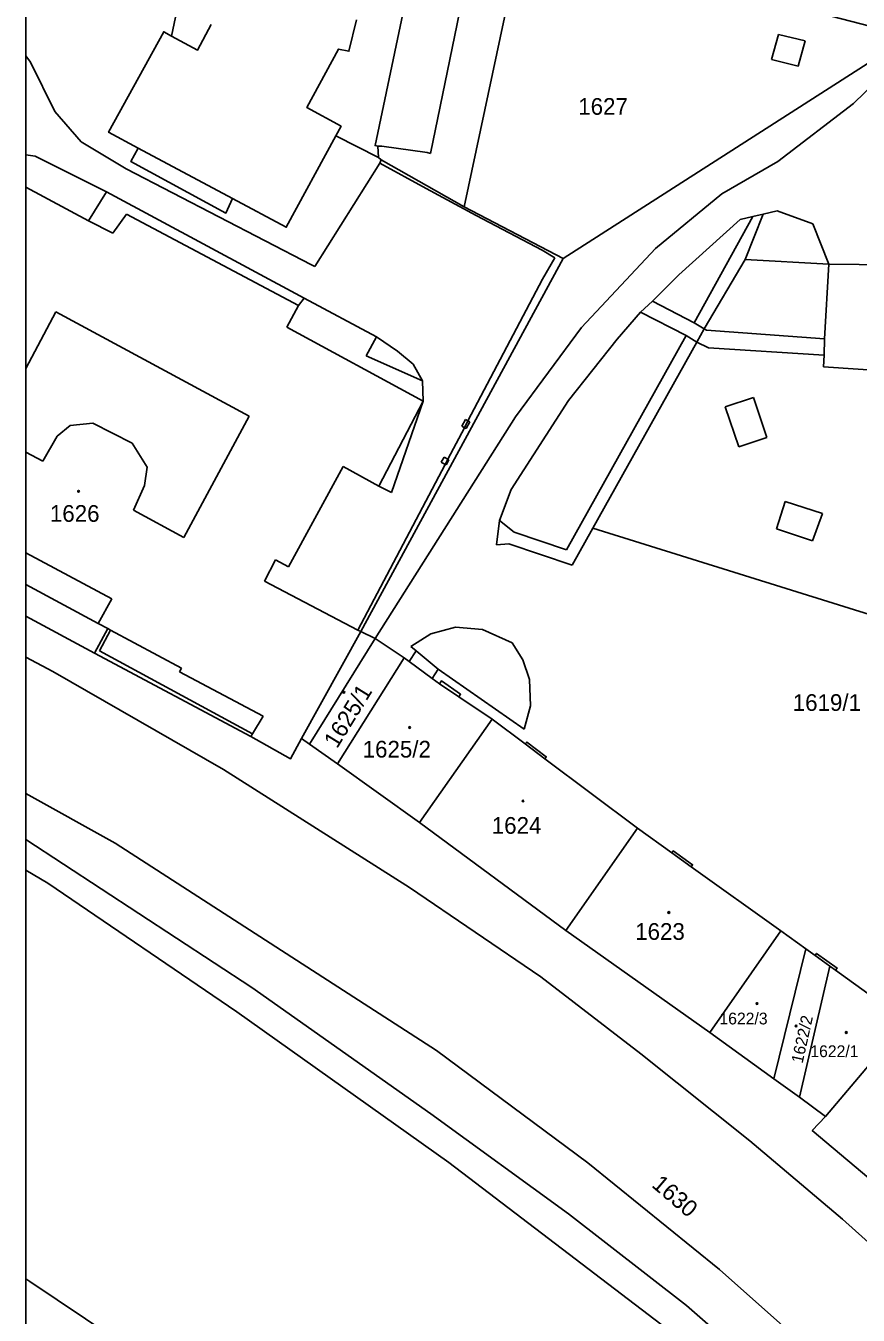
# Model space of a CAD drawing. Extents: x -598934 to -598196, y -1162208 to -1161502.
# Drawn here: x -598932 to -598847.2, y -1161742.9 to -1161611.7 of the extents above; entities that cross this region are included whole.
import ezdxf

# ---------------------------------------------------------------- set-up
doc = ezdxf.new("R2010")
doc.units = 0
for name, color, linetype in [('KN_CAR_KR', 7, 'Continuous'), ('KN_KULTURY', 7, 'Continuous'), ('KN_PARC_CIS_POZ', 7, 'Continuous'), ('KN_PARC_CIS_STAV', 7, 'Continuous'), ('KN_PARC_PLOCHA', 7, 'Continuous'), ('parcely_l', 7, 'Continuous')]:
    doc.layers.add(name, color=color, linetype=linetype)

msp = doc.modelspace()

# ---------------------------------------------------------------- linework, layer by layer
at = {"layer": 'KN_CAR_KR'}
for points in [[(-598886.11, -1161601.84), (-598890.79, -1161624.66)], [(-598856.06, -1161615.09), (-598855.34, -1161612.52)], [(-598855.34, -1161612.52), (-598852.61, -1161613.18)], [(-598852.61, -1161613.18), (-598853.33, -1161615.77)], [(-598847.69, -1161619.55), (-598841.83, -1161613.85)], [(-598931.53, -1161615.36), (-598932.02, -1161614.7)], [(-598929.05, -1161620.37), (-598931.53, -1161615.36)], [(-598853.33, -1161615.77), (-598856.06, -1161615.09)], [(-598855.42, -1161625.45), (-598847.69, -1161619.55)], [(-598929.05, -1161620.37), (-598926.37, -1161623.46)], [(-598926.37, -1161623.46), (-598921.78, -1161626.22)], [(-598932.02, -1161624.79), (-598931.06, -1161624.91)], [(-598920.57, -1161624.1), (-598910.96, -1161629.23)], [(-598895.75, -1161623.9), (-598896.15, -1161623.89)], [(-598895.75, -1161623.9), (-598891.14, -1161624.54)], [(-598891.14, -1161624.54), (-598890.79, -1161624.66)], [(-598931.06, -1161624.91), (-598923.81, -1161628.54)], [(-598895.95, -1161625.63), (-598902.56, -1161636.15)], [(-598895.95, -1161625.63), (-598895.81, -1161625.3)], [(-598891.23, -1161628.22), (-598895.95, -1161625.63)], [(-598861.13, -1161628.76), (-598855.42, -1161625.45)], [(-598902.9, -1161636), (-598921.78, -1161626.22)], [(-598932.02, -1161628.07), (-598925.62, -1161631.51)], [(-598925.62, -1161631.51), (-598923.81, -1161628.54)], [(-598923.81, -1161628.54), (-598903.67, -1161639.39)], [(-598886.15, -1161630.97), (-598891.23, -1161628.22)], [(-598867.86, -1161634.33), (-598861.13, -1161628.76)], [(-598923.14, -1161632.76), (-598921.75, -1161630.82)], [(-598921.75, -1161630.82), (-598904.23, -1161640.13)], [(-598879.42, -1161634.48), (-598886.15, -1161630.97)], [(-598859.26, -1161631.38), (-598865.48, -1161636.99)], [(-598857.96, -1161631.07), (-598863.92, -1161641.9)], [(-598859.26, -1161631.38), (-598857.96, -1161631.07)], [(-598856.92, -1161630.83), (-598858.75, -1161635.43)], [(-598857.96, -1161631.07), (-598856.92, -1161630.83)], [(-598856.92, -1161630.83), (-598855.48, -1161630.49)], [(-598851.83, -1161631.82), (-598855.48, -1161630.49)], [(-598925.62, -1161631.51), (-598923.14, -1161632.76)], [(-598851.83, -1161631.82), (-598850.21, -1161635.93)], [(-598878.13, -1161635.28), (-598879.42, -1161634.48)], [(-598879.37, -1161637.43), (-598878.13, -1161635.28)], [(-598875.42, -1161642.37), (-598867.86, -1161634.33)], [(-598902.56, -1161636.15), (-598902.9, -1161636)], [(-598850.21, -1161635.93), (-598850.65, -1161643.52)], [(-598886.97, -1161651.88), (-598879.37, -1161637.43)], [(-598865.48, -1161636.99), (-598868.19, -1161639.67)], [(-598904.23, -1161640.13), (-598905.44, -1161642.33)], [(-598903.67, -1161639.39), (-598904.23, -1161640.13)], [(-598903.67, -1161639.39), (-598896.29, -1161643.33)], [(-598868.19, -1161639.67), (-598869.39, -1161640.79)], [(-598868.19, -1161639.67), (-598863.92, -1161641.9)], [(-598932.02, -1161646.53), (-598928.94, -1161640.76)], [(-598928.94, -1161640.76), (-598909.26, -1161651.41)], [(-598869.39, -1161640.79), (-598871.76, -1161643.56)], [(-598864.74, -1161643.18), (-598869.39, -1161640.79)], [(-598863.92, -1161641.9), (-598862.92, -1161642.5)], [(-598905.44, -1161642.33), (-598891.52, -1161649.85)], [(-598882.13, -1161651.46), (-598875.42, -1161642.37)], [(-598864.74, -1161643.18), (-598876.93, -1161664.99)], [(-598863.67, -1161643.85), (-598864.74, -1161643.18)], [(-598862.92, -1161642.5), (-598862.67, -1161642.64)], [(-598862.67, -1161642.64), (-598850.65, -1161643.52)], [(-598897.34, -1161645.25), (-598896.29, -1161643.33)], [(-598896.29, -1161643.33), (-598894.14, -1161644.76)], [(-598876.73, -1161649.79), (-598871.76, -1161643.56)], [(-598863.67, -1161643.85), (-598862.47, -1161644.44)], [(-598850.68, -1161645.2), (-598862.47, -1161644.44)], [(-598850.65, -1161643.52), (-598850.68, -1161645.2)], [(-598891.6, -1161647.81), (-598897.34, -1161645.25)], [(-598894.14, -1161644.76), (-598892.56, -1161646.1)], [(-598850.68, -1161645.2), (-598850.77, -1161646.37)], [(-598892.56, -1161646.1), (-598891.6, -1161647.81)], [(-598850.77, -1161646.37), (-598823.48, -1161648.19)], [(-598891.6, -1161647.81), (-598891.52, -1161649.85)], [(-598876.73, -1161649.79), (-598882.56, -1161658.86)], [(-598860.79, -1161650.43), (-598857.88, -1161649.5)], [(-598857.88, -1161649.5), (-598856.52, -1161653.56)], [(-598891.52, -1161649.85), (-598896.06, -1161658.53)], [(-598891.52, -1161649.85), (-598894.77, -1161659.17)], [(-598859.38, -1161654.5), (-598860.79, -1161650.43)], [(-598928.81, -1161653.42), (-598927.48, -1161652.33)], [(-598925.19, -1161652.11), (-598927.48, -1161652.33)], [(-598921.17, -1161654.13), (-598925.19, -1161652.11)], [(-598909.26, -1161651.41), (-598915.91, -1161663.73)], [(-598882.13, -1161651.46), (-598896.44, -1161674.02)], [(-598887.6, -1161652.42), (-598887.24, -1161651.74)], [(-598887.33, -1161652.57), (-598887.6, -1161652.42)], [(-598887.33, -1161652.57), (-598886.97, -1161651.88)], [(-598887.24, -1161651.74), (-598886.97, -1161651.88)], [(-598886.79, -1161651.98), (-598887.16, -1161652.66)], [(-598886.97, -1161651.88), (-598886.79, -1161651.98)], [(-598928.81, -1161653.42), (-598930.28, -1161655.99)], [(-598889.02, -1161655.77), (-598887.33, -1161652.57)], [(-598887.16, -1161652.66), (-598887.33, -1161652.57)], [(-598856.52, -1161653.56), (-598859.38, -1161654.5)], [(-598930.28, -1161655.99), (-598932.02, -1161655.06)], [(-598921.17, -1161654.13), (-598919.64, -1161656.57)], [(-598898.18, -1161673.18), (-598889.3, -1161656.3)], [(-598889.72, -1161656.09), (-598889.39, -1161655.58)], [(-598889.3, -1161656.3), (-598889.72, -1161656.09)], [(-598889.39, -1161655.58), (-598889.02, -1161655.77)], [(-598889.3, -1161656.3), (-598889.02, -1161655.77)], [(-598889.2, -1161656.35), (-598889.3, -1161656.3)], [(-598888.91, -1161655.83), (-598889.2, -1161656.35)], [(-598889.02, -1161655.77), (-598888.91, -1161655.83)], [(-598919.93, -1161658.45), (-598919.64, -1161656.57)], [(-598899.68, -1161656.53), (-598905.24, -1161666.72)], [(-598896.06, -1161658.53), (-598899.68, -1161656.53)], [(-598921.05, -1161660.97), (-598919.93, -1161658.45)], [(-598894.77, -1161659.17), (-598896.06, -1161658.53)], [(-598883.77, -1161662), (-598882.56, -1161658.86)], [(-598855.55, -1161662.85), (-598854.65, -1161660.09)], [(-598854.65, -1161660.09), (-598850.85, -1161661.29)], [(-598915.91, -1161663.73), (-598921.05, -1161660.97)], [(-598850.85, -1161661.29), (-598851.89, -1161664.07)], [(-598883.77, -1161662), (-598884.08, -1161664.51)], [(-598882.28, -1161663.21), (-598883.77, -1161662)], [(-598876.36, -1161666.56), (-598874.24, -1161662.79)], [(-598851.89, -1161664.07), (-598855.55, -1161662.85)], [(-598876.93, -1161664.99), (-598882.28, -1161663.21)], [(-598932.02, -1161665.3), (-598923.24, -1161669.98)], [(-598884.08, -1161664.51), (-598882.81, -1161664.38)], [(-598882.81, -1161664.38), (-598876.36, -1161666.56)], [(-598906.57, -1161666.02), (-598907.71, -1161668.2)], [(-598905.24, -1161666.72), (-598906.57, -1161666.02)], [(-598907.71, -1161668.2), (-598898.18, -1161673.18)], [(-598932.02, -1161668.53), (-598924.63, -1161672.49)], [(-598923.24, -1161669.98), (-598924.63, -1161672.49)], [(-598925.01, -1161675.53), (-598923.66, -1161673.02)], [(-598923.66, -1161673.02), (-598924.63, -1161672.49)], [(-598924.52, -1161675.27), (-598923.37, -1161673.19)], [(-598923.37, -1161673.19), (-598923.66, -1161673.02)], [(-598916.14, -1161677.06), (-598923.37, -1161673.19)], [(-598898.18, -1161673.18), (-598897.88, -1161673.33)], [(-598888.23, -1161672.88), (-598890.75, -1161673.55)], [(-598888.23, -1161672.88), (-598885.49, -1161673.13)], [(-598882.47, -1161674.47), (-598885.49, -1161673.13)], [(-598903.12, -1161684.79), (-598896.44, -1161674.02)], [(-598892.78, -1161674.83), (-598890.75, -1161673.55)], [(-598882.47, -1161674.47), (-598881.37, -1161676.21)], [(-598932.02, -1161675.92), (-598929.26, -1161677.4)], [(-598908.92, -1161683.75), (-598924.52, -1161675.27)], [(-598892.97, -1161676.37), (-598892.24, -1161675.28)], [(-598892.24, -1161675.28), (-598892.78, -1161674.83)], [(-598892.24, -1161675.28), (-598890.01, -1161677.14)], [(-598929.26, -1161677.4), (-598911.88, -1161687.37)], [(-598916.35, -1161677.43), (-598916.14, -1161677.06)], [(-598890.01, -1161677.14), (-598890.63, -1161678.11)], [(-598881.25, -1161683.27), (-598890.01, -1161677.14)], [(-598880.71, -1161678.19), (-598881.37, -1161676.21)], [(-598907.85, -1161681.92), (-598916.35, -1161677.43)], [(-598887.9, -1161679.96), (-598889.87, -1161678.63)], [(-598880.71, -1161678.19), (-598880.61, -1161680.89)], [(-598881.25, -1161683.27), (-598880.61, -1161680.89)], [(-598908.92, -1161683.75), (-598907.85, -1161681.92)], [(-598909.09, -1161684.01), (-598908.92, -1161683.75)], [(-598879.15, -1161686.27), (-598881.14, -1161684.77)], [(-598911.88, -1161687.37), (-598892.94, -1161699.39)], [(-598932.02, -1161689.81), (-598922.91, -1161694.88)], [(-598908.99, -1161709.55), (-598932.02, -1161694.49)], [(-598890.19, -1161715.97), (-598922.91, -1161694.88)], [(-598864.23, -1161697.26), (-598866.21, -1161695.85)], [(-598892.94, -1161699.39), (-598879.55, -1161708.46)], [(-598849.53, -1161707.8), (-598850.1, -1161707.39)], [(-598869.36, -1161716.33), (-598879.55, -1161708.46)], [(-598908.99, -1161709.55), (-598890.77, -1161722.43)], [(-598890.19, -1161715.97), (-598874.78, -1161727.42)], [(-598869.36, -1161716.33), (-598858.27, -1161725.17)], [(-598876.72, -1161732.62), (-598890.77, -1161722.43)], [(-598858.27, -1161725.17), (-598848.83, -1161733.15)], [(-598861.34, -1161738.27), (-598874.78, -1161727.42)], [(-598876.72, -1161732.62), (-598864.7, -1161741.93)], [(-598834.64, -1161745.86), (-598848.83, -1161733.15)], [(-598861.34, -1161738.27), (-598850.63, -1161747.82)], [(-598864.7, -1161741.93), (-598839.67, -1161763.81)]]:
    msp.add_lwpolyline(points, dxfattribs=at)
at = {"layer": 'KN_KULTURY'}
for centre, radius in [((-598926.64, -1161659.05), 0.09), ((-598926.64, -1161659.05), 0.0398), ((-598899.62, -1161679.5), 0.09), ((-598899.62, -1161679.5), 0.0398), ((-598892.91, -1161683.09), 0.09), ((-598892.91, -1161683.09), 0.0398), ((-598881.37, -1161690.57), 0.09), ((-598881.37, -1161690.57), 0.0398), ((-598866.51, -1161701.93), 0.09), ((-598866.51, -1161701.93), 0.0398), ((-598857.53, -1161711.2), 0.09), ((-598857.53, -1161711.2), 0.0398), ((-598853.55, -1161713.48), 0.09), ((-598853.55, -1161713.48), 0.0398), ((-598848.44, -1161714.14), 0.09), ((-598848.44, -1161714.14), 0.0398)]:
    msp.add_circle(centre, radius, dxfattribs=at)
at = {"layer": 'KN_PARC_PLOCHA'}
for points in [[(-598907.97, -1161569.08), (-598917.18, -1161612.69), (-598917.96, -1161612.26), (-598923.58, -1161622.49), (-598920.57, -1161624.1), (-598921.32, -1161625.46), (-598911.63, -1161630.71), (-598910.96, -1161629.23), (-598905.49, -1161632.16), (-598900.43, -1161622.86), (-598896.1, -1161625.05), (-598895.81, -1161625.3), (-598887.35, -1161630.07), (-598877.29, -1161635.33), (-598897.88, -1161673.33), (-598903.94, -1161684.22), (-598905.05, -1161686.28), (-598909.09, -1161684.01), (-598925.01, -1161675.53), (-598932.02, -1161671.76), (-598932.02, -1161526.32)], [(-598913.14, -1161611.53), (-598914.54, -1161614.14), (-598917.18, -1161612.69), (-598907.97, -1161569.08)], [(-598891.02, -1161598.13), (-598896.44, -1161623.85), (-598896.15, -1161623.89), (-598896.1, -1161625.05), (-598900.43, -1161622.86), (-598899.89, -1161621.87), (-598903.38, -1161619.97), (-598900.15, -1161614.03), (-598899.1, -1161614.24), (-598898.32, -1161611.04)], [(-598881.6, -1161602.96), (-598887.35, -1161630.07), (-598895.81, -1161625.3), (-598896.1, -1161625.05), (-598896.15, -1161623.89), (-598896.44, -1161623.85), (-598891.02, -1161598.13)], [(-598898.32, -1161611.04), (-598899.1, -1161614.24), (-598900.15, -1161614.03), (-598903.38, -1161619.97), (-598899.89, -1161621.87), (-598900.43, -1161622.86), (-598905.49, -1161632.16), (-598910.96, -1161629.23), (-598911.63, -1161630.71), (-598921.32, -1161625.46), (-598920.57, -1161624.1), (-598923.58, -1161622.49), (-598917.96, -1161612.26), (-598917.18, -1161612.69), (-598914.54, -1161614.14), (-598913.14, -1161611.53)], [(-598842.34, -1161713), (-598849.53, -1161707.8), (-598849.38, -1161707.59), (-598851.47, -1161706.09), (-598851.62, -1161706.29), (-598852.55, -1161705.62), (-598855.09, -1161703.78), (-598864.23, -1161697.26), (-598864.09, -1161697.06), (-598866.06, -1161695.65), (-598866.21, -1161695.85), (-598869.71, -1161693.35), (-598879.15, -1161686.27), (-598879, -1161686.07), (-598880.99, -1161684.57), (-598881.14, -1161684.77), (-598884.52, -1161682.24), (-598887.9, -1161679.96), (-598887.72, -1161679.71), (-598889.67, -1161678.35), (-598889.87, -1161678.63), (-598890.63, -1161678.11), (-598892.97, -1161676.37), (-598893.47, -1161675.99), (-598896.44, -1161674.02), (-598897.88, -1161673.33), (-598877.29, -1161635.33), (-598841.96, -1161612.75)], [(-598847.12, -1161635.94), (-598850.21, -1161635.93), (-598858.75, -1161635.43), (-598862.92, -1161642.5), (-598863.67, -1161643.85), (-598874.24, -1161662.79), (-598844.45, -1161672.1)], [(-598844.45, -1161672.1), (-598874.24, -1161662.79), (-598863.67, -1161643.85), (-598862.92, -1161642.5), (-598858.75, -1161635.43), (-598850.21, -1161635.93), (-598847.12, -1161635.94)], [(-598861.19, -1161748.52), (-598888.91, -1161727.38), (-598910.52, -1161712.03), (-598929.76, -1161698.95), (-598932.02, -1161697.6), (-598932.02, -1161671.76), (-598925.01, -1161675.53), (-598909.09, -1161684.01), (-598905.05, -1161686.28), (-598903.94, -1161684.22), (-598903.12, -1161684.79), (-598900.27, -1161686.79), (-598891.92, -1161692.76), (-598877.01, -1161703.75), (-598862.32, -1161714.13), (-598855.8, -1161718.86), (-598853.21, -1161720.74), (-598850.54, -1161722.68), (-598851.91, -1161724.11), (-598842.52, -1161732.01), (-598833.54, -1161739.94), (-598820.14, -1161752.25)], [(-598737.15, -1161925.8), (-598813.1, -1161843.8), (-598846.83, -1161807.87), (-598870.15, -1161785.99), (-598874.43, -1161782.02), (-598909.01, -1161754.64), (-598931.6, -1161739.49), (-598932.02, -1161739.21), (-598932.02, -1161697.6), (-598929.76, -1161698.95), (-598910.52, -1161712.03), (-598888.91, -1161727.38), (-598861.19, -1161748.52), (-598845.68, -1161761.08), (-598825.17, -1161781.28), (-598821.65, -1161784.92), (-598808.06, -1161799.42), (-598788.14, -1161822.37), (-598718.78, -1161901.85)]]:
    msp.add_lwpolyline(points, dxfattribs=at)
for points in [[(-598841.96, -1161612.75), (-598877.29, -1161635.33), (-598887.35, -1161630.07), (-598881.6, -1161602.96), (-598858.7, -1161608.73), (-598849.97, -1161610.68)], [(-598893.47, -1161675.99), (-598900.27, -1161686.79), (-598903.12, -1161684.79), (-598903.94, -1161684.22), (-598897.88, -1161673.33), (-598896.44, -1161674.02)], [(-598884.52, -1161682.24), (-598891.92, -1161692.76), (-598900.27, -1161686.79), (-598893.47, -1161675.99), (-598892.97, -1161676.37), (-598890.63, -1161678.11), (-598889.87, -1161678.63), (-598889.67, -1161678.35), (-598887.72, -1161679.71), (-598887.9, -1161679.96)], [(-598869.71, -1161693.35), (-598877.01, -1161703.75), (-598891.92, -1161692.76), (-598884.52, -1161682.24), (-598881.14, -1161684.77), (-598880.99, -1161684.57), (-598879, -1161686.07), (-598879.15, -1161686.27)], [(-598855.09, -1161703.78), (-598862.32, -1161714.13), (-598877.01, -1161703.75), (-598869.71, -1161693.35), (-598866.21, -1161695.85), (-598866.06, -1161695.65), (-598864.09, -1161697.06), (-598864.23, -1161697.26)], [(-598852.55, -1161705.62), (-598855.8, -1161718.86), (-598862.32, -1161714.13), (-598855.09, -1161703.78)], [(-598851.62, -1161706.29), (-598850.1, -1161707.39), (-598853.21, -1161720.74), (-598855.8, -1161718.86), (-598852.55, -1161705.62)], [(-598842.34, -1161713), (-598850.54, -1161722.68), (-598853.21, -1161720.74), (-598850.1, -1161707.39), (-598851.62, -1161706.29), (-598851.47, -1161706.09), (-598849.38, -1161707.59), (-598849.53, -1161707.8)], [(-598827.5, -1161714.52), (-598827.73, -1161714.79), (-598834.54, -1161722.64), (-598842.52, -1161732.01), (-598851.91, -1161724.11), (-598850.54, -1161722.68), (-598842.34, -1161713), (-598841.61, -1161712.29), (-598836.61, -1161706.38), (-598836.41, -1161706.15), (-598832.84, -1161709.51)], [(-598870.15, -1161785.99), (-598871.79, -1161787.66), (-598873.42, -1161789.39), (-598879.44, -1161795.83), (-598885.94, -1161790.72), (-598895.69, -1161782.65), (-598903.31, -1161777.5), (-598919.33, -1161766.5), (-598924.65, -1161762.85), (-598923.28, -1161760.72), (-598932.02, -1161754.06), (-598932.02, -1161749.37), (-598931.02, -1161748.07), (-598932.02, -1161747.26), (-598932.02, -1161739.21), (-598931.6, -1161739.49), (-598909.01, -1161754.64), (-598874.43, -1161782.02)]]:
    msp.add_lwpolyline(points, close=True, dxfattribs=at)
at = {"layer": 'parcely_l'}
for points in [[(-598932.02, -1161671.76), (-598932.02, -1161526.32)], [(-598917.18, -1161612.69), (-598907.97, -1161569.08)], [(-598886.91, -1161578.75), (-598891.02, -1161598.13), (-598896.44, -1161623.85), (-598896.15, -1161623.89), (-598896.1, -1161625.05)], [(-598887.35, -1161630.07), (-598881.6, -1161602.96), (-598858.7, -1161608.73), (-598849.97, -1161610.68), (-598841.96, -1161612.75)], [(-598913.14, -1161611.53), (-598914.54, -1161614.14), (-598917.18, -1161612.69)], [(-598900.43, -1161622.86), (-598899.89, -1161621.87), (-598903.38, -1161619.97), (-598900.15, -1161614.03), (-598899.1, -1161614.24), (-598898.32, -1161611.04)], [(-598917.18, -1161612.69), (-598917.96, -1161612.26), (-598923.58, -1161622.49), (-598920.57, -1161624.1), (-598921.32, -1161625.46), (-598911.63, -1161630.71), (-598910.96, -1161629.23), (-598905.49, -1161632.16), (-598900.43, -1161622.86)], [(-598877.29, -1161635.33), (-598841.96, -1161612.75)], [(-598896.1, -1161625.05), (-598900.43, -1161622.86)], [(-598896.1, -1161625.05), (-598895.81, -1161625.3), (-598887.35, -1161630.07)], [(-598877.29, -1161635.33), (-598887.35, -1161630.07)], [(-598897.88, -1161673.33), (-598877.29, -1161635.33)], [(-598778.16, -1161666.6), (-598778.49, -1161666.91), (-598790.74, -1161678.44), (-598797.36, -1161682.69), (-598802.7, -1161683.85), (-598808.26, -1161683.41), (-598841.51, -1161673.02), (-598844.45, -1161672.1), (-598874.24, -1161662.79), (-598863.67, -1161643.85), (-598862.92, -1161642.5), (-598858.75, -1161635.43), (-598850.21, -1161635.93), (-598847.12, -1161635.94), (-598846.25, -1161636)], [(-598932.02, -1161697.6), (-598932.02, -1161671.76)], [(-598932.02, -1161671.76), (-598925.01, -1161675.53), (-598909.09, -1161684.01), (-598905.05, -1161686.28), (-598903.94, -1161684.22)], [(-598897.88, -1161673.33), (-598903.94, -1161684.22)], [(-598893.47, -1161675.99), (-598896.44, -1161674.02), (-598897.88, -1161673.33)], [(-598900.27, -1161686.79), (-598893.47, -1161675.99)], [(-598884.52, -1161682.24), (-598887.9, -1161679.96), (-598887.72, -1161679.71), (-598889.67, -1161678.35), (-598889.87, -1161678.63), (-598890.63, -1161678.11), (-598892.97, -1161676.37), (-598893.47, -1161675.99)], [(-598891.92, -1161692.76), (-598884.52, -1161682.24)], [(-598884.52, -1161682.24), (-598881.14, -1161684.77), (-598880.99, -1161684.57), (-598879, -1161686.07), (-598879.15, -1161686.27), (-598869.71, -1161693.35)], [(-598903.94, -1161684.22), (-598903.12, -1161684.79), (-598900.27, -1161686.79)], [(-598900.27, -1161686.79), (-598891.92, -1161692.76)], [(-598877.01, -1161703.75), (-598891.92, -1161692.76)], [(-598869.71, -1161693.35), (-598877.01, -1161703.75)], [(-598855.09, -1161703.78), (-598864.23, -1161697.26), (-598864.09, -1161697.06), (-598866.06, -1161695.65), (-598866.21, -1161695.85), (-598869.71, -1161693.35)], [(-598932.02, -1161739.21), (-598932.02, -1161697.6)], [(-598932.02, -1161697.6), (-598929.76, -1161698.95), (-598910.52, -1161712.03), (-598888.91, -1161727.38), (-598861.19, -1161748.52), (-598845.68, -1161761.08), (-598825.17, -1161781.28)], [(-598877.01, -1161703.75), (-598862.32, -1161714.13)], [(-598862.32, -1161714.13), (-598855.09, -1161703.78)], [(-598852.55, -1161705.62), (-598855.09, -1161703.78)], [(-598852.55, -1161705.62), (-598855.8, -1161718.86)], [(-598853.21, -1161720.74), (-598850.1, -1161707.39), (-598851.62, -1161706.29)], [(-598851.62, -1161706.29), (-598852.55, -1161705.62)], [(-598842.34, -1161713), (-598849.53, -1161707.8), (-598849.38, -1161707.59), (-598851.47, -1161706.09), (-598851.62, -1161706.29)], [(-598862.32, -1161714.13), (-598855.8, -1161718.86)], [(-598850.54, -1161722.68), (-598842.34, -1161713)], [(-598855.8, -1161718.86), (-598853.21, -1161720.74)], [(-598853.21, -1161720.74), (-598850.54, -1161722.68)], [(-598842.52, -1161732.01), (-598851.91, -1161724.11), (-598850.54, -1161722.68)], [(-598870.15, -1161785.99), (-598874.43, -1161782.02), (-598909.01, -1161754.64), (-598931.6, -1161739.49), (-598932.02, -1161739.21)], [(-598932.02, -1161747.26), (-598932.02, -1161739.21)]]:
    msp.add_lwpolyline(points, dxfattribs=at)

# ---------------------------------------------------------------- texts
at = {"layer": 'KN_PARC_CIS_POZ'}
for s, p in [('1627', (-598875.74, -1161620.71)), ('1619/1', (-598853.89, -1161681.4))]:
    msp.add_text(s, height=1.7, dxfattribs=at).set_placement(p)
msp.add_text('1630', height=1.7, rotation=319.5005, dxfattribs=at).set_placement((-598868.35, -1161729.79))
at = {"layer": 'KN_PARC_CIS_STAV'}
for s, height, p in [('1626', 1.7, (-598929.56, -1161662.15)), ('1625/2', 1.7, (-598897.7, -1161686.15)), ('1624', 1.7, (-598884.55, -1161693.91)), ('1623', 1.7, (-598869.94, -1161704.71)), ('1622/3', 1.2, (-598861.36, -1161713.32)), ('1622/1', 1.2, (-598852.1, -1161716.65))]:
    msp.add_text(s, height=height, dxfattribs=at).set_placement(p)
for s, height, rotation, p in [('1625/1', 1.7, 58.37, (-598900.31, -1161685.31)), ('1622/2', 1.2, 77.4002, (-598852.89, -1161717.35))]:
    msp.add_text(s, height=height, rotation=rotation, dxfattribs=at).set_placement(p)

doc.saveas('drawing.dxf')
